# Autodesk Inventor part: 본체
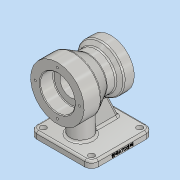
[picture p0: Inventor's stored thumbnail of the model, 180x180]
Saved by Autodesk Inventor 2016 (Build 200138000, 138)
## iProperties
Created: 2019-01
Part Number: 본체
Material: 알루미늄 6061
Document SubType Name: Modeling
Designer: Administrator
Density: 2.7 g/cm^3
Appearance: 알루미늄 - 평지
Mass: 898.703 g
Surface Area: 601.268 cm^2
Volume: 332.853 cm^3
Author: Administrator
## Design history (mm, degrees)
sketch "스케치1"
  geometry: L1 (46, 46)-(-46, 46); L2 (-46, 46)-(-46, -46); L3 (-46, -46)-(46, -46); L4 (46, -46)-(46, 46); 4 further points
  constraints: 8 end point, 3 midpoint, 2 parallel, 2 perpendicular, 2 vertical alignment, 1 horizontal, 1 horizontal alignment
  dimensions: "d0" = 92 distance of L3.end L1.start
extrude "돌출1" new body sketch "스케치1" distance "d1" = 10; taper "d2" = 0 deg
sketch "스케치2"
  geometry: L1 (0, 46)-(10, 46) reference; L2 (0, -46)-(10, -46) reference; L3 (0, -46)-(0, 46) reference; L4 (80, 51)-(80, -29); L5 (80, 51)-(120, 51); L6 (120, 51)-(120, 26); L7 (120, 26)-(108, 5.215); L8 (108, 5.215)-(108, -8.126); L9 (108, -8.126)-(115, -14); L10 (115, -14)-(115, -29); L11 (115, -29)-(80, -29); 3 further points
  constraints: 16 end point, 3 vertical, 2 midpoint, 2 perpendicular, 1 horizontal
  dimensions: "d8" = 5 distance from line of L1 L4.start; "d9" = 80 distance of L4.start L4.end; "d10" = 80 distance between parallel lines of L3 L4; "d11" = 25 distance of L5.end L6.end; "d16" = 15 distance of L9.end L10.end; "d17" = 50 deg angle of L9 L8; "d18" = 30 deg angle of L7 L8; "d19" = 80 diameter of L6 L4; "d20" = 70 diameter of L10 L4; "d22" = 56 diameter of L8 L4
revolve "회전1" sketch "스케치2" stored, may be unused: angle "d23" = 90 deg
sketch "스케치3"
  geometry: L1 (-46, -46)-(46, -46) reference; L2 (-46, 46)-(-46, -46) reference; C1 r 16 at (0, -16); 1 further point
  constraints: 1 centre point
  dimensions: "d24" = 30 distance from line of L1 C1.centre; "d25" = 46 distance from line of C1.centre L2; "d26" = 32 diameter of C1
extrude "돌출2" join sketch "스케치3" distance "d27" = 50; taper "d28" = 0 deg
sketch "스케치4"
  geometry: L1 (45, -14)-(115, -14) reference; L2 (45, -29)-(115, -29) reference; L3 (45, -14)-(45, -29) reference; L4 (45, -19.679)-(10, -36); L5 (10, -46)-(10, 46) reference; L6 (0, -46)-(10, -46) reference; L7 (45, -19.679)-(62.664, 4.234); L8 (62.664, 4.234)-(10, 4.234); L9 (10, 4.234)-(10, -36); 1 further point
  constraints: 8 end point, 3 point on line, 1 collinear, 1 horizontal
  dimensions: "d29" = 10 distance from line of L6 L4.end; "d30" = 115 deg angle of L5 L4; "d31" = 23.9132 vertical distance of L4.start L7.end; "d32" = 52.66371 distance of L7.end L8.end
extrude "돌출3" join sketch "스케치4" stored distance "d33" = 10; taper "d34" = 0 deg
sketch "스케치5"
  geometry: L1 (40, 51)-(120, 51) reference; L2 (80, 51)-(80, -29); L3 (45, -29)-(115, -29) reference; L4 (80, 51)-(106, 51); L5 (106, 51)-(106, 32); L6 (105, 31)-(96, 31); L7 (96, 31)-(96, -12); L8 (96, -12)-(99.4, -12); L9 (100, -12.6)-(100, -29); L10 (80, -29)-(100, -29); A1 r 1 centre (105, 32) between (105, 31) and (106, 32); A2 r 0.6 centre (99.4, -12.6) between (100, -12.6) and (99.4, -12); 3 further points
  constraints: 16 end point, 6 point on line, 4 perpendicular, 4 point on circle, 4 tangent, 2 centre point, 2 midpoint, 2 vertical
  dimensions: "d35" = 20 distance of L4.end point (106, 31); "d36" = 17 distance of point (100, -12) L9.end; "d37" = 52 diameter of L5 L2; "d38" = 40 diameter of L9 L2; "d39" = 32 diameter of L7 L2; "d40" = 1 radius of A1; "d41" = 0.6 radius of A2
revolve "회전2" sketch "스케치5" stored, may be unused: angle "d42" = 90 deg
chamfer "모따기1" distance "d43" = 1; stored, may be unused: second distance "d44" = 2, angle "d45" = 45 deg
sketch "스케치6"
  geometry: A1 r 28 centre (0, 0) between (11.819, -25.383) and (-11.819, -25.383) reference; A2 r 40 centre (0, 0) between (12.49, -38) and (-12.49, -38) reference; A3 r 40 centre (0, 0) between (12.49, -38) and (-12.49, -38) reference; A4 r 33 centre (0, 0) between (-33, 0) and (33, 0); 3 further points
  constraints: 4 point on circle, 2 horizontal alignment, 2 vertical alignment, 1 centre point, 1 coincident, 2 other
  dimensions: "d47" = 66 diameter of A4
hole "구멍1" sketch "스케치6" at (-33, 0), (33, 0), (0, 33), (0, -33) diameter "d48" = 3.242; stored, may be unused: countersink angle "d52" = 90 deg, drill point angle "d54" = 118 deg; dims "d49" = 9, "d50" = 4, "d51" = 2, "d53" = 11
sketch "스케치7"
  geometry: A1 r 35 centre (0, 0) between (5, -34.641) and (-5, -34.641) reference; A2 r 27.5 centre (0, 0) between (27.5, 0) and (-27.5, 0); 3 further points
  constraints: 4 point on circle, 2 horizontal alignment, 2 vertical alignment, 1 centre point, 1 coincident
  dimensions: "d55" = 27.5 radius of A2
hole "구멍2" sketch "스케치7" at (27.5, 0), (-27.5, 0), (0, -27.5), (0, 27.5) diameter "d56" = 3.242; stored, may be unused: countersink angle "d60" = 90 deg, drill point angle "d62" = 118 deg; dims "d57" = 9, "d58" = 4, "d59" = 2, "d61" = 11
fillet "모깎기1" dims "d63" = 10
hole "구멍3" diameter "d66" = 9; stored, may be unused: countersink angle "d70" = 82 deg, drill point angle "d72" = 118 deg; dims "d64" = 10, "d65" = 10, "d67" = 9, "d68" = 3.023, "d69" = 2, "d71" = 11
hole "구멍4" diameter "d75" = 9; stored, may be unused: countersink angle "d79" = 82 deg, drill point angle "d81" = 118 deg; dims "d73" = 10, "d74" = 10, "d76" = 9, "d77" = 3.023, "d78" = 2, "d80" = 11
hole "구멍5" diameter "d84" = 9; stored, may be unused: countersink angle "d88" = 82 deg, drill point angle "d90" = 118 deg; dims "d82" = 10, "d83" = 10, "d85" = 9, "d86" = 3.023, "d87" = 2, "d89" = 11
hole "구멍6" diameter "d93" = 9; stored, may be unused: countersink angle "d97" = 82 deg, drill point angle "d99" = 118 deg; dims "d91" = 10, "d92" = 10, "d94" = 9, "d95" = 3.023, "d96" = 2, "d98" = 11
sketch "스케치8"
  geometry: L1 (0, 0)-(72, 0) reference; 3 further points
  constraints: 1 midpoint, 1 vertical alignment, 1 other
  dimensions: "d100" = 4 distance from line of L1 point (36, 4)
feature "엠보싱1" sketch "스케치8" dims "d0" = 92, "d8" = 5, "d9" = 80, "d10" = 80, "d11" = 25, "d16" = 15, "d17" = 50 deg, "d18" = 30 deg, "d19" = 80, "d20" = 70, "d22" = 56, "d101" = 0.5, "d102" = 0
fillet "모깎기2" dims "d103" = 3
fillet "모깎기3" dims "d104" = 3
fillet "모깎기4" dims "d105" = 3
fillet "모깎기5" dims "d106" = 3
fillet "모깎기6" dims "d107" = 3
node "솔리드1"
node "투영된 루프1"
node "투영된 루프2"
